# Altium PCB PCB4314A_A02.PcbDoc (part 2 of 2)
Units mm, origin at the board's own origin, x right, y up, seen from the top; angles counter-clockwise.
Board outline 35.56 x 55.88 mm, 2 copper layers (Top Layer, Bottom Layer), stack 1.57 mm thick; 98 components, 71 nets, 413 pads, 418 vias.
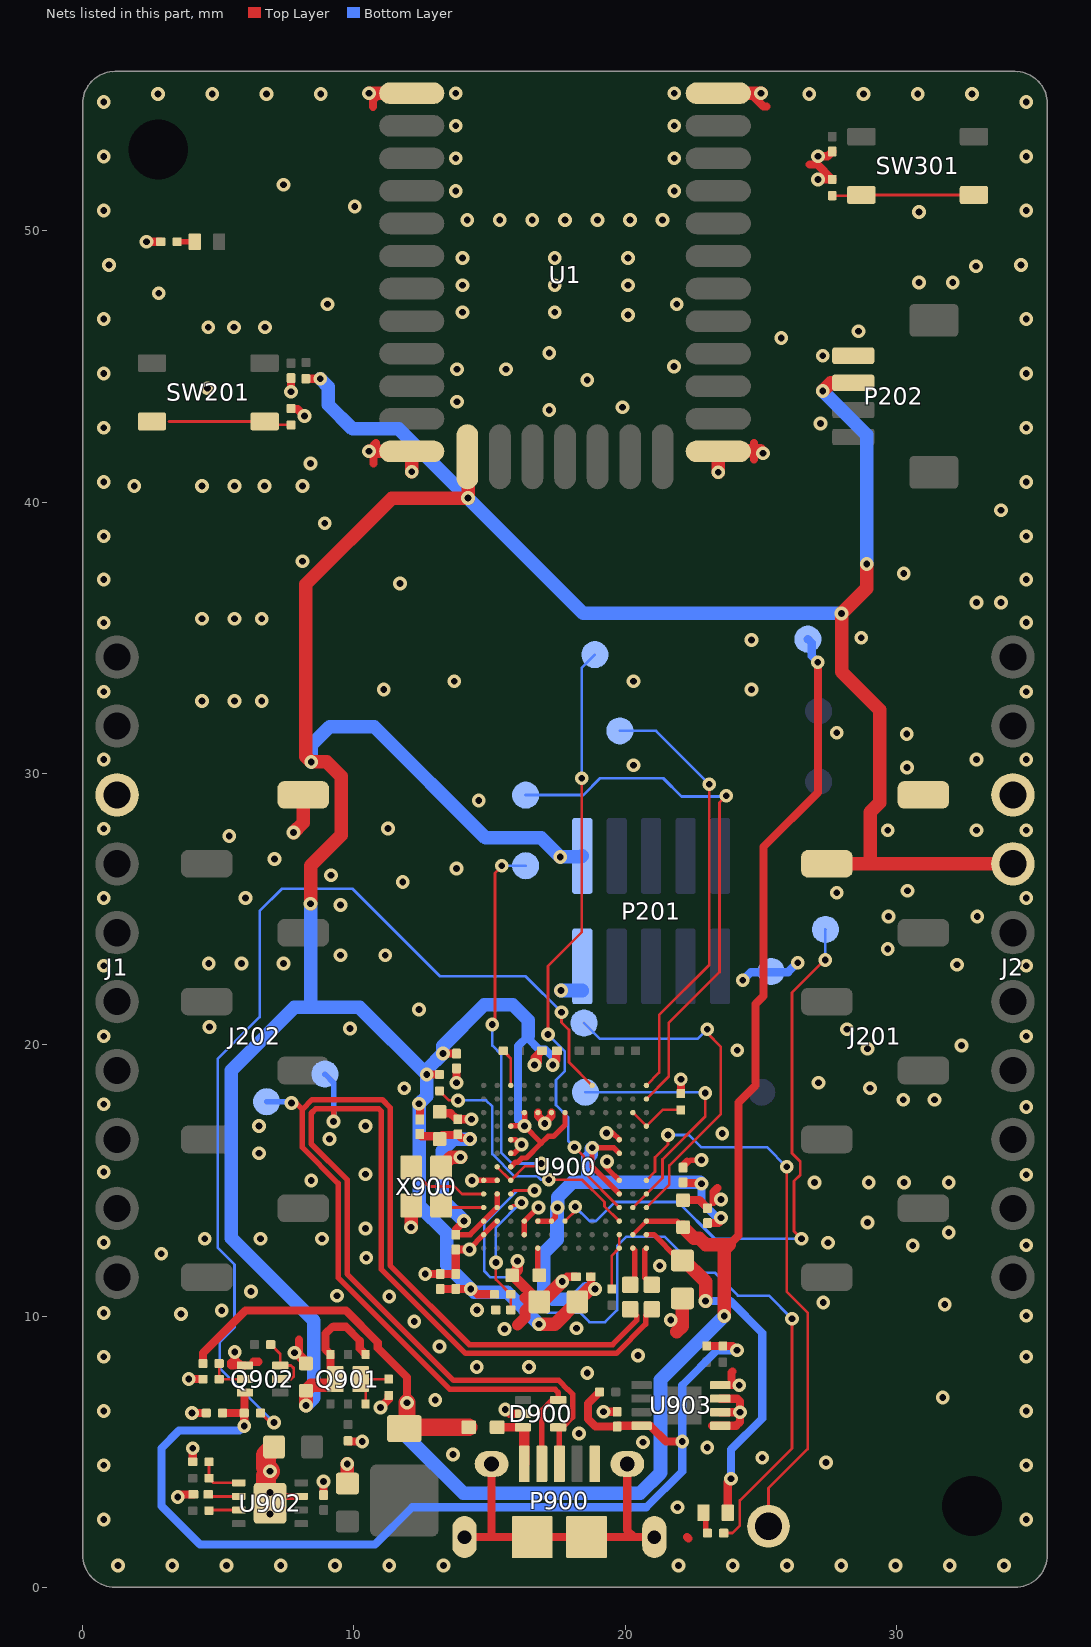
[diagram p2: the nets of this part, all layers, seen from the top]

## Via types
v1: diameter 0.508, hole 0.25, Top Layer to Bottom Layer, tented both sides, 418 vias

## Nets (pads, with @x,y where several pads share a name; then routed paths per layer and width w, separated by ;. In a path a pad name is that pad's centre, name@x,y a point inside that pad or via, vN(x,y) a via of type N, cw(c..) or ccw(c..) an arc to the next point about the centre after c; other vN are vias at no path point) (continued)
CTRL_MCU_PB10: R905.1 U900.L9 | length 30.2
  Top Layer w0.1: U900.L9@15.78,14.5 15.905,14.625 v1(16.655,14.625) ; R905.1@23.63,2 23.95,2 24.225,2.275 24.225,3.2 26.15,5.125 v1(26.15,9.9)
  Bottom Layer w0.1: v1(16.655,14.625) 16.023,14.625 14.802,13.404 14.802,11.654 15.031,11.425 15.85,11.425 17.15,10.125 18.325,10.125 18.675,9.775 19.25,9.775 19.7,10.225 19.7,12.575 20.05,12.925 21.45,12.925 22.775,11.6 23.3,11.6 24.15,10.75 25.3,10.75 v1(26.15,9.9)
CTRL_MCU_PB13: U900.N9 X900.3 | length 3.1
  Top Layer w0.1: X900.3@12.106,15.475 12.106,15.425 12.756,14.775 13.706,14.775 13.981,14.5 U900.N9@14.78,14.5
CTRL_MCU_PB14: U900.N10 X900.1 | length 1.7
  Top Layer w0.1: X900.1@13.231,14.04 13.201,14.07 X900.1@13.206,14.075 13.281,14 U900.N10@14.78,14
CTRL_MCU_PC2: R921.1 U900.L1 | length 1.4
  Top Layer w0.1: R921.1@15.505,19.775 15.515,19.775 15.612,19.678 15.612,19.668 15.78,19.5 U900.L1@15.78,18.5
CTRL_MCU_PC14: R922.1 U900.C12 U900.C13 | length 2.1
  Top Layer w0.1: R922.1@19.506,11 19.506,12.226 U900.C13@19.78,12.5 U900.C12@19.78,13
CTRL_MCU_PD0: C923.1 R901.1 U900.L10 | length 5.4
  Top Layer w0.1: v1(15.231,11.975) 15.231,11.349 R901.1@15.78,10.8 C923.1@15.78,10.225 ; U900.L10@15.78,14 15.855,14.075 16.055,14.075 v1@16.288,14.308
  Bottom Layer w0.1: v1(15.231,11.975) 15.231,13.26 v1@16.204,14.233 ; v1@16.204,14.201 v1@16.204,14.233 ; v1@16.205,14.268 16.223,14.251 v1@16.204,14.233 ; v1@16.281,14.326 v1@16.288,14.326
  other v1: 16.18,14.175
CTRL_MCU_PE4: R931.1 U900.C11 | length 9.7
  Top Layer w0.1: R931.1@13.155,18.3 13.505,17.95 v1(13.831,17.95) ; v1(17.181,15.025) 18.408,15.025 19.237,14.196 19.237,14.043 U900.C11@19.78,13.5
  Bottom Layer w0.1: v1(13.831,17.95) 14.875,17.95 15.1,17.725 15.1,15.975 15.925,15.15 16.775,15.15 16.9,15.025 v1(17.181,15.025)
CTRL_MCU_PE11: R935.1 U900.A4 U900.B3 | length 2.2
  Top Layer w0.1: U900.B3@20.28,17.5 U900.A4@20.78,17 21.38,17.6 R935.1@22.05,17.6
CTRL_MCU_PF5: TP999.1 U900.A8 | length 21
  Top Layer w0.1: U900.A8@20.78,15 21.1,15.32 21.1,15.85 21.575,16.325 v1(21.575,16.675) ; TP999.1@25.28,2.25 25.28,3.655 26.725,5.1 26.725,10.125 25.95,10.9 v1(25.95,15.5)
  Bottom Layer w0.1: v1(21.575,16.675) 22.35,16.675 22.8,16.225 25.225,16.225 v1(25.95,15.5)
CTRL_MCU_PF10: R903.2 U900.B13 | length 1.5
  Top Layer w0.2: R903.2@20.18,11.15 20.357,11.327 20.357,12.423 U900.B13@20.28,12.5
CTRL_MCU_PF11: R904.2 U900.A13 | length 1.5
  Top Layer w0.2: U900.A13@20.78,12.5 20.719,12.44 20.719,11.411 R904.2@20.98,11.15
CTRL_MCU_RESET: TPJ17.1 U900.L8 U900.M7 | length 15.5
  Top Layer w0.1: v1(15.1,20.75) 15.2,20.85 15.2,26.325 v1@15.475,26.6 ; U900.M7@15.28,15.5 U900.L8@15.78,15 16.305,15.525 16.8,15.525 v1(16.9,15.625)
  Bottom Layer w0.1: v1(15.1,20.75) 15.1,19.975 15.425,19.65 15.425,16.025 15.825,15.625 v1(16.9,15.625) ; v1(15.45,26.6) TPJ17.1@16.33,26.6
CTRL_MCU_RXD: TPJ6.1 U900.A1 | length 16.2
  Top Layer w0.1: U900.A1@20.78,18.5 21.25,18.97 21.25,21.1 23.1,22.95 v1(23.1,29.6)
  Bottom Layer w0.1: TPJ6.1@19.8,31.57 21.13,31.57 v1(23.1,29.6)
CTRL_MCU_SWCLK: TPJ2.1 U900.C10 | length 22.4
  Top Layer w0.1: v1(17.15,20.375) 17.15,22.9 18.4,24.15 v1@18.4,29.775 ; v1(18.125,16.225) 18.475,15.875 18.475,15.305 U900.C10@19.78,14
  Bottom Layer w0.1: v1(17.15,20.375) 17.775,19.75 17.775,19.025 17.45,18.7 17.45,17.775 17.9,17.325 17.9,16.45 v1(18.125,16.225) ; v1(18.4,29.825) 18.4,33.9 TPJ2.1@18.88,34.38
CTRL_MCU_SWDIO: TPJ1.1 U900.A9 U900.B10 | length 9.8
  Top Layer w0.1: U900.B10@20.28,14 U900.A9@20.78,14.5 21.375,15.095 21.375,15.775 22.95,17.35 v1(22.95,18.225)
  Bottom Layer w0.1: TPJ1.1@18.53,18.25 22.925,18.25 v1(22.95,18.225)
CTRL_MCU_SWO: TPJ3.1 U900.A10 | length 12.8
  Top Layer w0.1: U900.A10@20.78,14 21.625,14.845 21.625,15.55 23.525,17.45 23.525,19.925 23.025,20.425 v1(23.025,20.575)
  Bottom Layer w0.1: TPJ3.1@18.48,20.8 19.055,20.225 22.675,20.225 v1(23.025,20.575)
CTRL_MCU_TEST_MODE: TPJ11.1 U900.G11 | length 22.5
  Top Layer w0.1: U900.G11@17.78,13.5 18.23,13.95 v1@18.23,14.175
  Top Layer w0.102: v1(26.5,12.85) 26.225,13.125 26.225,14.975 26.45,15.2 26.45,15.7 26.15,16 26.15,21.925 27.35,23.125 v1(27.375,23.125)
  Bottom Layer w0.102: v1(18.156,14.025) 18.681,13.5 18.925,13.5 19.625,14.2 21.95,14.2 23.3,12.85 v1(26.5,12.85) ; v1(27.375,23.125) 27.375,24.245 TPJ11.1@27.38,24.25
CTRL_MCU_TXD: TPJ5.1 U900.A2 | length 20.3
  Top Layer w0.1: U900.A2@20.78,18 21.6,18.82 21.6,20.8 23.475,22.675 23.475,28.925 v1(23.725,29.175)
  Bottom Layer w0.1: TPJ5.1@16.33,29.2 16.325,29.205 18.455,29.205 19.075,29.825 21.4,29.825 22.075,29.15 23.7,29.15 v1(23.725,29.175)
CTRL_MCU_USB_DM: D900.5 P900.2 R903.1 TPJ19.1 | length 41.4
  Top Layer w0.203: v1(7.7,17.85) 7.857,17.85 8.095,17.612 ; P900.2@16.925,4.55 16.925,6.52 17.305,6.9 D900.5@17.53,6.9 17.53,7.178 17.413,7.295 13.538,7.295 9.42,11.413 9.42,14.888 8.095,16.213 8.095,17.612 ; R903.1@20.18,10.25 20.42,10.01 20.42,9.837 19.533,8.95 14.25,8.95 11.33,11.87 11.33,17.687 11.042,17.975 8.458,17.975 8.095,17.612
  Bottom Layer w0.203: TPJ19.1@6.78,17.9 v1@7.6,17.9
CTRL_MCU_USB_DP: D900.4 P900.3 R904.1 TPJ18.1 | length 42.4
  Top Layer w0.203: v1(9.25,17.175) 9.25,17.645 ; P900.3@17.575,4.55 17.575,5.855 D900.4@17.53,5.9 17.68,5.9 18.057,6.277 18.057,6.675 18.059,6.677 18.059,7.116 18.059,7.123 17.903,7.279 17.896,7.279 17.55,7.625 13.675,7.625 9.75,11.55 9.75,15.025 8.425,16.35 8.425,17.475 8.595,17.645 9.25,17.645 ; R904.1@20.98,10.25 20.75,10.02 20.75,9.7 19.67,8.62 14.113,8.62 11,11.733 11,17.55 10.905,17.645 9.25,17.645
  Bottom Layer w0.203: TPJ18.1@8.93,18.92 9.25,18.6 v1@9.25,17.275
CTRL_MCU_WAKEUP: R929.1 U900.E1 | length 38
  Top Layer w0.1: R929.1@6.555,6.425 6.565,6.425 6.915,6.075 v1(7.056,6.075) ; v1(17.65,21.2) 17.65,20.825 17.925,20.55 17.925,19.355 U900.E1@18.78,18.5
  Bottom Layer w0.1: v1(7.056,6.075) 5.05,8.081 5.05,9.025 5.6,9.575 5.6,11.9 4.975,12.525 4.975,19.475 6.525,21.025 6.525,24.925 7.35,25.75 9.95,25.75 13.175,22.525 16.325,22.525 v1(17.65,21.2)
DBG_3V3: C919.1 Q902.3 R910.2 R911.2 R912.2 R929.2 R933.1 U903.8 | length 40.4
  Top Layer w0.3: R933.1@5.155,6.425 R929.2@5.955,6.425 5.957,6.425 5.967,6.435 5.967,7.175 Q902.3@5.98,7.175 ; v1@5.956,5.951 R929.2@5.955,6.425 ; R912.2@19.05,7.2 18.625,6.775 18.625,6.2 18.9,5.925 C919.1@19.7,5.925 19.73,5.955 U903.8@20.602,5.955 20.92,5.955 21.5,5.375 v1(22.1,5.375) ; R911.2@23,8.9 R910.2@23.6,8.9 23.96,8.9 v1(24.121,8.739)
  Bottom Layer w0.3: v1(5.956,5.95) 5.781,5.775 3.55,5.775 2.9,5.125 2.9,3 4.325,1.575 10.775,1.575 12.15,2.95 20.775,2.95 22.1,4.275 v1(22.1,5.375) 22.1,7.45 23.389,8.739 v1(24.121,8.739)
DBG_VBUS: C901.1 D901.2 L901.2 R917.2 TPJ12.1 U900.A11 U900.B12 | length 63.1
  Top Layer w0.152: U900.B12@20.28,13 U900.A11@20.78,13.5
  Top Layer w0.2: U900.A11@20.78,13.5 21.905,13.5 C901.1@22.13,13.275
  Top Layer w0.3: R917.2@4.431,8.25 4.431,8.631 6,10.2 9.705,10.2 10.875,9.03 10.875,8.825 11.956,7.744 v1(11.956,6.8) ; 23.825,12.625 24.175,12.975 24.175,17.875 24.8,18.5 24.8,21.5 25.1,21.8 25.1,27.3 27.1,29.3 27.1,30.475 v1(27.1,34.1)
  Top Layer w0.5: C901.1@22.13,13.275 22.535,12.87 22.73,12.87 22.975,12.625 23.825,12.625 23.65,12.45 v1(23.65,10)
  Top Layer w0.635: D901.2@11.855,5.85 D901.2@11.905,5.9 ; v1(11.956,6.8) 11.956,5.951 D901.2@11.905,5.9 ; L901.2@14.23,5.9 D901.2@11.905,5.9
  Bottom Layer w0.3: TPJ12.1@26.73,34.95 26.875,34.805 26.875,34.325 v1(27.1,34.1)
  Bottom Layer w0.5: v1(11.956,6.8) 11.956,5.544 14.025,3.475 20.558,3.475 21.3,4.217 21.3,7.65 v1(23.65,10)
DBG_VREGO: C902.1 LED900.1 U900.A12 | length 13.3
  Top Layer w0.2: U900.A12@20.78,13 21.055,13 C902.1@21.93,12.125
  Top Layer w0.3: LED900.1@23.78,2.75 23.78,3.88 v1(23.9,4)
  Top Layer w0.305: C902.1@21.93,12.125 C902.1@22.105,12.125
  Top Layer w0.5: C902.1@22.105,12.125 22.96,11.27 v1(22.96,10.55)
  Bottom Layer w0.3: v1(22.96,10.55) 23.875,10.55 25.05,9.375 25.05,6.225 23.9,5.075 v1(23.9,4)
GND: C201.2 C301.2 C900.2 C901.2 C902.2 C903.2 C904.2 C905.2 C907.2 C908.2 C909.2 C910.2 C911.2 C915.2 C916.2 C917.2 C918.2 C919.2 C920.2 C923.2 C924.2 C925.2 C926.2 D900.2 J1.3 J2.3 J201.8 J202.8 P201.2 P202.1 P900.5 P900.6 P900.7 P900.8 P900.9 P900.10 P900.11 Q902.1 R202.2 R203.1 R301.1 R909.1 R915.1 R916.1 R933.2 R934.1 R935.2 TPJ13.1 U1.1 U1.12 U1.20 U1.31 U900.C5 U900.C8 U900.H3 U900.J3 U900.K11 U900.K12 U900.L5 U900.L6 U900.M8 U900.M11 U900.N8 U900.N12 U902.3 U902.9 U903.1 U903.2 U903.3 U903.4 X900.2 X900.4 | length 73.9
  Top Layer w0.1: C903.2@13.155,17.525 C903.2@13.18,17.5
  Top Layer w0.2: v1@14.255,17.15 v1@14.381,17.15 ; v1(14.254,12.451) 14.256,12.476 U900.N12@14.78,13 U900.M11@15.28,13.5 ; v1(14.356,15) U900.N8@14.78,15 U900.M8@15.28,15 ; U900.L6@15.78,16 15.903,16 16.179,16.276 15.956,16.5 U900.L5@15.78,16.5 ; U900.K12@16.28,13 U900.K11@16.28,13.5 16.805,14.025 16.855,14.025 v1@16.88,14.05 ; v1@19.274,15.709 v1@19.317,15.709 ; v1(19.307,16.749) 19.531,16.749 U900.C5@19.78,16.5 ; v1@19.33,15.722 v1@19.317,15.709 ; U900.C8@19.78,15 19.374,15.406 ; C910.2@22.151,15.454 C910.2@22.13,15.475 C910.2@22.13,15.495 ; 22.275,15.75 22.13,15.605 C910.2@22.13,15.495 ; v1(22.806,15.75) 22.405,15.75 22.21,15.555 22.19,15.555 C910.2@22.13,15.495 ; v1@19.255,15.646 19.374,15.527 19.374,15.406 ; v1@19.255,15.646 19.255,15.525 19.374,15.406 ; v1@19.255,15.647 v1@19.317,15.709
  Top Layer w0.25: U902.9@7.155,3.35 U902.3@8.055,3.35
  Top Layer w0.3: v1(2.356,49.6) 2.86,49.6 2.87,49.61 R203.1@2.88,49.6 ; v1(3.506,3.325) 3.606,3.425 C918.2@4.081,3.425 ; v1(3.906,7.675) R916.1@4.431,7.675 ; v1(4.031,6.425) R933.2@4.555,6.425 ; R909.1@4.056,4.625 v1(4.056,5.125) ; 5.476,8.287 5.476,8.175 Q902.1@5.98,8.175 ; v1(5.606,8.675) 5.606,8.399 Q902.1@5.83,8.175 ; 6.3,8.325 6.312,8.313 6.48,8.313 ; v1(7.806,8.65) 7.931,8.65 v1@7.975,8.606 ; 7.975,9.125 v1@7.975,8.606 ; C920.2@8.231,8.25 7.975,8.506 v1@7.975,8.606 ; C920.2@8.331,8.25 v1@7.975,8.606 ; C916.2@8.88,3.4 C916.2@8.881,3.401 ; C916.2@8.881,3.402 v1@8.881,3.849 ; R915.1@9.781,5.4 9.781,5.39 9.791,5.38 10.301,5.38 v1(10.306,5.375) ; 10.7,54.575 10.7,54.825 U1.1@10.95,55.075 ; 10.725,41.425 10.725,41.875 10.725,42.093 10.812,42.18 ; v1(10.975,6.625) 11.28,6.93 R934.1@11.28,7.075 ; C925.2@13.78,19.125 C925.2@13.78,19.125 v1(13.781,18.6) ; P900.8@14.075,1.85 15.005,1.85 ; P900.6@15.075,4.55 15.075,1.92 15.005,1.85 ; 16.775,19.6 16.775,19.369 v1(16.656,19.25) 16.656,19.521 16.91,19.775 C908.2@16.93,19.775 ; v1(17.681,11.275) 17.856,11.45 C911.2@18.181,11.45 ; P900.7@20.075,4.55 20.075,2.105 20.33,1.85 ; P900.9@21.075,1.85 20.33,1.85 ; R935.2@22.05,18.2 v1(22.05,18.725) ; C901.2@22.13,14.275 22.73,14.275 C926.2@23.03,13.975 ; 22.275,1.85 22.325,1.8 ; 23.25,14.2 23.25,14.575 23.4,14.725 ; U903.4@23.502,7.455 24.195,7.455 v1(24.2,7.45) ; 23.916,7.682 23.916,7.916 23.95,7.95 ; U1.31@24.6,55.075 25.092,54.584 25.208,54.584 ; 24.748,41.57 24.748,41.9 24.748,42.18 ; 26.8,52.45 27.08,52.45 R301.1@27.63,51.9 ; v1(27.106,51.9) R301.1@27.63,51.9 ; v1(27.106,52.75) 27.455,52.75 27.6,52.895 27.62,52.895 27.63,52.905 C301.2@27.63,52.925 ; R301.1@27.62,51.92 27.63,51.91 R301.1@27.63,51.9 ; 15.005,1.85 P900.10@16.575,1.85 P900.11@18.575,1.85 20.33,1.85
  Top Layer w0.305: R202.2@7.68,43.45 7.68,43.44 7.687,43.432 7.924,43.432 v1(8.181,43.175) ; C201.2@7.68,44.575 7.681,44.574 v1(7.681,44.075) ; v1(12.63,11.55) C909.2@13.18,11.55 C924.2@13.755,11.55 C904.2@13.755,12.45 14.255,12.45 v1(14.254,12.451) ; C903.2@13.155,17.475 13.564,17.475 13.745,17.294 13.786,17.294 C905.2@13.83,17.25 14.228,17.25 v1@14.255,17.223 ; v1(14.254,12.451) v1(14.254,12.451) ; v1@14.28,12.475 v1(14.254,12.451) ; v1(15.58,6.55) 15.73,6.4 D900.2@16.23,6.4 ; U900.J3@16.78,17.5 16.78,17.374 17.031,17.123 17.28,17.371 U900.H3@17.28,17.5 ; v1(19.2,6.475) C919.2@19.7,6.475 ; U903.1@23.205,5.955 U903.1@23.502,5.955 23.505,5.958 24.089,5.958 24.226,6.095 v1@24.226,6.455 ; U903.3@23.502,6.955 23.505,6.953 24.128,6.953 24.226,6.855 v1@24.226,6.455 ; U903.2@23.505,6.458 U903.2@23.502,6.455 v1@24.226,6.455
  Top Layer w0.4: 16.025,9.675 16.3,9.95 16.3,10.2 C907.2@16.625,10.525 ; v1(16.03,12.032) 16.03,11.7 C900.2@15.83,11.5 15.856,11.5 C907.2@16.831,10.525 C907.2@16.625,10.525 ; 16.3,10.675 16.45,10.525 C907.2@16.625,10.525
  Top Layer w0.5: J1.3@1.246,29.21 J1.3@1.27,29.21 ; v1(7.775,27.825) 8.129,28.179 J202.8@8.129,29.21 ; C915.2@9.755,3.825 9.756,3.826 v1(9.756,4.55) ; v1(10.556,41.875) 10.725,41.875 U1.12@12.13,41.875 12.131,41.874 v1(12.131,41.125) ; v1(10.556,55.075) 10.95,55.075 U1.1@12.13,55.075 ; v1(12.106,13.275) X900.4@12.106,14.075 ; X900.2@13.206,15.475 13.581,15.85 v1(13.931,15.85) ; C907.2@16.831,10.525 16.931,10.525 v1(17.681,11.275) ; 21.9,9.425 22.106,9.631 C902.2@22.106,10.65 ; U1.31@23.43,55.075 24.6,55.075 v1(25.004,55.075) ; v1(23.431,41.1) 23.431,41.874 U1.20@23.43,41.875 23.455,41.9 24.748,41.9 v1@24.981,41.9 ; J201.8@30.381,29.21 J201.8@30.989,29.21
  Top Layer w0.75: U902.9@6.905,3.5 U902.9@6.905,3.1 6.755,3.25 6.755,4.124 v1(6.906,4.275) 6.755,4.426 6.755,4.875 C917.2@7.055,5.175
  Bottom Layer w0.305: v1@15.98,12.082 v1(16.03,12.032) ; v1(24.331,22.375) 24.631,22.675 26.006,22.675 v1(26.356,23.025)
  Bottom Layer w0.5: v1(17.631,22) 18.406,22 P201.2@18.416,21.99
  other v1: 1.3,0.8 3.3,0.8 5.3,0.8 7.3,0.8 9.3,0.8 11.3,0.8 13.3,0.8 21.96,0.8 23.96,0.8 25.96,0.8 27.96,0.8 29.96,0.8 31.96,0.8 33.96,0.8 0.775,2.5 34.785,2.5 6.906,2.7 21.925,2.95 6.906,3.5 8.881,3.9 0.775,4.5 34.785,4.5 27.4,4.6 25.05,4.775 13.65,4.9 23.025,5.15 20.65,5.35 18.3,5.675 24.231,6.45 0.775,6.5 34.785,6.5 13,6.9 31.7,7 18.6,7.9 14.525,8.125 16.45,8.125 0.775,8.5 34.785,8.5 20.475,8.55 13.15,8.875 15.55,9.525 18.2,9.55 12.225,9.8 21.675,9.85 34.785,10.01 3.625,10.075 0.775,10.11 5.125,10.2 14.531,10.225 31.775,10.425 27.3,10.5 11.3,10.725 9.375,10.75 6.2,10.9 21.275,11.85 10.45,12.15 2.9,12.3 30.6,12.6 34.785,12.61 27.475,12.7 0.775,12.71 4.5,12.85 6.55,12.85 8.825,12.85 31.925,13.075 10.425,13.225 28.925,13.45 16.806,14 23.531,14.3 26.975,14.925 28.975,14.925 30.275,14.925 31.925,14.925 8.425,15 34.785,15.21 10.425,15.225 0.775,15.31 19.33,15.7 6.5,16 16.18,16.325 9.1,16.525 23.576,16.732 6.5,17 10.425,17 17.031,17.1 14.331,17.25 34.785,17.71 0.775,17.81 30.25,17.975 31.4,17.975 11.85,18.4 29.025,18.4 27.125,18.6 24.125,19.8 28.925,19.85 32.4,19.975 0.775,20.31 34.785,20.31 28.175,20.575 9.85,20.6 4.675,20.65 12.4,21.3 0.775,22.91 34.785,22.91 32.225,22.95 4.65,23 5.85,23 7.4,23 9.5,23.3 11.15,23.3 29.675,23.525 29.7,24.725 32.975,24.725 9.5,25.15 0.775,25.41 6,25.41 34.785,25.41 27.8,25.6 30.4,25.675 11.8,26 9.15,26.25 13.775,26.5 7.075,26.85 5.4,27.7 29.675,27.91 32.95,27.91 34.785,27.91 0.775,27.96 11.25,27.975 14.6,29 30.381,30.225 20.3,30.3 0.775,30.51 32.95,30.51 34.785,30.51 30.375,31.45 27.8,31.5 4.4,32.675 5.6,32.675 6.6,32.675 0.775,33.01 34.785,33.01 11.1,33.1 24.65,33.1 13.7,33.4 20.3,33.4 24.65,34.925 28.7,35 0.775,35.56 34.785,35.562 4.4,35.7 5.6,35.7 6.6,35.7 32.95,36.3 33.85,36.3 11.7,37 0.775,37.148 34.785,37.148 30.266,37.376 8.1,37.825 0.775,38.748 34.785,38.748 8.925,39.225 33.85,39.7 1.9,40.6 4.4,40.6 5.6,40.6 6.7,40.6 8.1,40.6 0.775,40.748 34.785,40.748 8.4,41.425 25.076,41.802 0.775,42.748 34.785,42.748 27.2,42.9 17.2,43.4 19.9,43.5 13.8,43.7 4.6,44.2 18.6,44.5 0.775,44.748 34.785,44.748 13.8,44.9 15.6,44.9 21.8,45 27.281,45.4 17.2,45.5 25.75,46.05 28.6,46.3 4.625,46.45 5.575,46.45 6.725,46.45 0.775,46.748 34.785,46.748 20.1,46.9 14,47 17.4,47 9.025,47.3 21.9,47.3 2.8,47.7 14,48 17.4,48 20.1,48 30.825,48.1 32.075,48.1 32.925,48.7 0.975,48.748 34.585,48.748 14,49 17.4,49 20.1,49 14.175,50.4 15.375,50.4 16.575,50.4 17.775,50.4 18.975,50.4 20.175,50.4 21.375,50.4 30.825,50.7 0.775,50.748 34.785,50.748 10.025,50.9 13.75,51.475 21.81,51.475 7.4,51.7 13.75,52.675 21.81,52.675 0.775,52.748 34.785,52.748 13.75,53.875 21.81,53.875 0.775,54.748 34.785,54.748 2.775,55.048 4.775,55.048 6.775,55.048 8.775,55.048 26.785,55.048 28.785,55.048 30.785,55.048 32.785,55.048 13.75,55.075 21.81,55.075
N16782098: LED201.2 R203.2 | length 0.7
  Top Layer w0.2: R203.2@3.48,49.6 LED201.2@4.13,49.6
N16786878: R202.1 SW201.3 SW201.4 | length 4.6
  Top Layer w0.1: 3.181,42.975 SW201.4@6.705,42.975 6.83,42.85 R202.1@7.68,42.85
N16788367: D900.3 L901.1 P900.1 | length 2.2
  Top Layer w0.3: L901.1@15.28,5.9 D900.3@16.155,5.9 ; D900.3@16.23,5.9 16.23,5.825 D900.3@16.275,5.78
  Top Layer w0.4: P900.1@16.275,4.55 D900.3@16.275,5.78
N16788394: R908.1 R909.2 U902.5 | length 1.8
  Top Layer w0.1: R909.2@4.656,4.625 R908.1@4.656,4.025 4.831,3.85 U902.5@5.755,3.85
N16788408: R907.1 U902.7 | length 1.1
  Top Layer w0.1: R907.1@4.656,2.825 4.681,2.85 U902.7@5.755,2.85
N16788424: C918.1 U902.6 | length 1.2
  Top Layer w0.1: C918.1@4.631,3.425 4.706,3.35 U902.6@5.755,3.35
N16791923: LED900.2 R905.2 | length 0.9
  Top Layer w0.2: LED900.2@22.88,2.675 LED900.2@22.88,2.75 22.96,2.67 22.96,2.06 23.02,2 R905.2@23.03,2
N16793325: C900.1 U900.J13 | length 1
  Top Layer w0.2: C900.1@16.78,11.5 U900.J13@16.78,12.5
N16793347: C903.1 C904.1 C905.1 L900.2 U900.M9 U900.M10 U900.N11 | length 9.4
  Top Layer w0.2: C904.1@13.755,13 14.28,13 U900.N11@14.78,13.5 U900.M10@15.28,14 U900.M9@15.28,14.5
  Top Layer w0.3: C904.1@13.755,13 13.755,13.199 v1(14.056,13.5)
  Top Layer w0.305: L900.2@12.43,16.705 12.43,16.68 12.487,16.623 13.057,16.623 C903.1@13.105,16.575 ; C903.1@13.155,16.525 C903.1@13.105,16.575 ; C905.1@13.83,16.7 13.83,16.68 13.822,16.672 13.252,16.672 13.155,16.575 C903.1@13.105,16.575 ; C905.1@13.83,16.7 13.831,16.679 13.838,16.672 13.858,16.672 13.966,16.564 14.292,16.564 v1@14.331,16.525
  Bottom Layer w0.5: v1(14.056,13.5) 13.256,14.3 13.256,16.1 13.68,16.523 14.28,16.523 v1(14.281,16.525)
N16822845: R301.2 SW301.3 SW301.4 | length 5.2
  Top Layer w0.1: R301.2@27.63,51.3 28.68,51.3 SW301.3@28.705,51.325 SW301.4@32.855,51.325
N16862939: Q901.3 Q901.8 R934.2 | length 2
  Top Layer w0.1: Q901.3@10.43,6.763 10.43,7.491 Q901.8@10.246,7.675 R934.2@11.28,7.675
N16974649: Q902.2 R916.2 R917.1 | length 1.5
  Top Layer w0.1: R917.1@5.031,8.25 R916.2@5.031,7.675 Q902.2@5.98,7.675
N16974657: Q902.5 Q902.6 R918.1 | length 2.3
  Top Layer w0.1: R918.1@6.93,8.95 6.94,8.95 7.28,8.61 Q902.6@7.28,8.175 7.681,8.175 7.781,8.075 7.781,7.775 7.681,7.675 Q902.5@7.28,7.675
VMCU: C907.1 C908.1 C909.1 C910.1 C911.1 C920.1 C924.1 C925.1 C926.1 J2.4 J201.7 L900.1 P201.1 P202.2 Q901.4 Q901.6 Q901.7 R201.1 R901.2 R931.2 U1.13 U900.C6 U900.C9 U900.G3 U900.H11 U900.J11 U900.K3 U900.L4 U900.L7 | length 172.8
  Top Layer w0.2: U900.L7@15.78,15.5 15.955,15.675 16.038,15.675 16.188,15.825 16.357,15.825 16.904,16.371 ; U900.L4@15.78,17 15.8,17.02 v1@16.23,17.02 ; v1@16.23,17 16.288,17.058 16.288,17.492 U900.K3@16.28,17.5 ; v1(16.281,17) 16.904,16.378 16.904,16.371 ; U900.J11@16.78,13.5 U900.H11@17.28,13.5 17.426,13.646 v1@17.426,13.796 ; U900.G3@17.78,17.5 17.78,17.049 17.352,16.621 17.153,16.621 16.904,16.371 ; v1@18.776,15.979 18.776,15.504 U900.C9@19.78,14.5 ; v1(18.781,16.2) 19.58,16.2 U900.C6@19.78,16
  Top Layer w0.25: v1@18.907,11.049 v1@18.956,11
  Top Layer w0.3: R201.1@8.23,44.55 v1(8.756,44.55) ; Q901.7@9.313,7.675 9.313,7.843 9.13,8.027 Q901.6@9.13,8.588 8.95,8.767 8.95,9.35 9.2,9.6 9.258,9.6 9.262,9.604 9.7,9.604 10.215,9.09 10.215,8.803 Q901.4@10.43,8.588 ; v1(12.4,17.825) 12.43,17.795 L900.1@12.43,17.245 ; v1(12.681,18.9) R931.2@13.155,18.9 ; C909.1@13.18,11 C924.1@13.755,11 v1(14.306,11) 14.362,11 14.56,10.803 15.177,10.803 R901.2@15.18,10.8 ; v1(13.281,19.675) C925.1@13.78,19.675 ; v1@17.456,19.431 17.456,19.765 17.466,19.775 C908.1@17.48,19.775 ; v1@18.681,11 18.731,11.05 C911.1@18.731,11.45 ; C910.1@22.13,14.925 22.13,14.91 22.14,14.9 22.781,14.9 v1(22.806,14.875) ; C926.1@23.03,13.425 23.431,13.425 v1@23.506,13.5
  Top Layer w0.5: v1(8.231,6.7) C920.1@8.231,7.25 C920.1@8.431,7.45 ; v1(8.4,25.2) 8.4,26.6 9.525,27.725 9.525,29.9 9,30.425 v1(8.425,30.425) 8.225,30.625 8.225,36.975 11.4,40.15 v1(14.206,40.15) 14.206,41.649 U1.13@14.18,41.675 ; 8.531,7.45 9.257,7.45 9.313,7.506 Q901.7@9.313,7.675 ; v1(16.825,9.7) 17.406,9.7 C907.1@18.231,10.525 18.231,10.55 18.681,11 v1@18.832,11 ; v1(27.281,44.1) 27.581,44.4 P202.2@28.405,44.4 ; J201.7@27.433,26.67 29,26.67 ; v1@28.895,37.7 28.895,36.82 v1(27.975,35.9) 27.975,33.75 29.375,32.35 29.375,28.925 29.025,28.575 29.025,26.695 29,26.67 ; 31.55,26.675 31.545,26.67 ; J2.4@34.29,26.67 31.545,26.67 ; 29,26.67 31.545,26.67
  Bottom Layer w0.3: v1(16.281,17) 16.05,17.231 16.05,19.95 16.425,20.325 16.425,20.225 16.825,19.825 17.05,19.825 17.331,19.544 v1(17.331,19.25) ; v1(22.806,14.875) 22.806,14.194 23.375,13.625 v1(23.531,13.625)
  Bottom Layer w0.5: v1(8.231,6.7) 8.525,6.994 8.525,9.825 5.475,12.875 5.475,19.05 7.8,21.375 8.4,21.375 ; v1(8.4,25.2) 8.4,21.375 ; v1(8.425,30.425) 8.425,31.05 9.1,31.725 10.75,31.725 14.85,27.625 16.906,27.625 v1(17.606,26.925) 18.381,26.925 P201.1@18.416,26.96 ; v1(8.756,44.55) 8.756,44.548 9.056,44.248 9.056,43.594 9.95,42.7 11.65,42.7 14.2,40.15 v1(14.206,40.15) 18.456,35.9 v1(27.975,35.9) ; 16.425,20.325 16.425,20.9 15.85,21.475 14.8,21.475 13.281,19.956 v1(13.281,19.675) 12.681,19.075 v1(12.681,18.9) ; v1(16.825,9.7) 15.65,10.875 14.431,10.875 v1(14.306,11) 13.425,11.881 13.425,13.05 12.4,14.075 v1(12.4,17.825) 12.681,18.106 v1(12.681,18.9) ; v1(18.781,16.2) 18.754,16.173 18.754,15.964 18.625,15.835 18.625,14.925 ; v1(18.882,11) 18.55,11 18.175,10.625 17.325,10.625 17,10.95 17,12.325 17.485,12.81 17.485,13.979 v1(17.506,14) 17.506,14.381 18.05,14.925 18.625,14.925 ; v1(22.806,14.875) 22.756,14.925 18.625,14.925 ; v1(27.281,44.1) 28.895,42.487 v1@28.895,37.75 ; 8.4,21.375 10.206,21.375 v1(12.681,18.9)
  other v1: 28.9,37.725
pads on no net: D900.1 M900.7 M900.9 M901.1 M902.1 P202.5 P202.6 P900.4 U1.21 U900.A3 U900.A5 U900.A7 U900.B1 U900.B2 U900.B4 U900.B5 U900.B6 U900.B7 U900.B8 U900.B9 U900.B11 U900.C3 U900.C4 U900.C7 U900.D2 U900.D13 U900.E2 U900.E11 U900.E12 U900.E13 U900.F1 U900.F2 U900.F3 U900.F11 U900.F12 U900.G1 U900.G2 U900.G12 U900.H1 U900.H2 U900.J1 U900.J2 U900.K1 U900.K2 U900.K13 U900.L3 U900.L11 U900.L12 U900.L13 U900.M2 U900.M3 U900.M4 U900.M5 U900.M6 U900.M12 U900.M13 U900.N3 U900.N4 U900.N5 U900.N6 U900.N7 U900.N13 U902.8 U903.9

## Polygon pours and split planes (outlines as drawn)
GND on Top Layer "GND_L1" (solid, remove dead copper, pour order 52): 0,0 0,55.88 35.56,55.88 35.56,0
GND on Bottom Layer "GND_L4" (solid, remove dead copper, pour order 46): 0,0 0,55.88 35.56,55.88 35.56,0

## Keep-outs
Bottom Layer:
  circle w0.1: c28.63,22 r0.5
  circle w0.1: c26.23,26.75 r0.5
  circle w0.1: c19.8,29.05 r0.5
  circle w0.1: c17.27,31.53 r0.5
  circle w0.1: c16.38,33.9 r0.5
  circle w0.1: c24.625,42.635 r0.3

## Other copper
Top Layer:
  pour cut-out: 22.35,10.525 22.35,9.475 23.475,9.475 23.475,10.525
  pour cut-out: 24.225,48.2 24.1,48.2 24.1,48.775 24.225,48.775
  pour cut-out: 22.6,47.675 22.6,44.4 23.1,44.4 23.1,47.675
  pour cut-out: 12.95,43.275 12.95,44.1 12.65,44.1 12.65,43.275
  pour cut-out: 14.5,42.225 14.5,42.475 21.175,42.475 21.175,42.225
  pour cut-out: 14.1,24.1 17.2,24.1 17.2,24 16.2,23 14.1,23
  pour cut-out: 13.9,18.9 21.2,18.9 21.2,12.1 13.9,12.1
  region: 34.13,47.7 34.13,44.05 29.63,44.05 29.63,47.7
  region: 29.63,40.1 29.63,43.75 34.13,43.75 34.13,40.1
  region net BGM220P_RESETN: 33.53,54.15 33.53,52.75 31.43,52.75 31.43,54.15
  region net N16822845: 33.53,52 33.53,50.6 31.43,50.6 31.43,52
  region net N16822845: 28.03,50.65 28.03,52.05 30.13,52.05 30.13,50.65
  region net BGM220P_RESETN: 28.03,52.8 28.03,54.2 30.13,54.2 30.13,52.8
  region net N16786878: 5.28,42.3 5.28,43.7 7.38,43.7 7.38,42.3
  region net N16786878: 1.88,42.3 1.88,43.7 3.98,43.7 3.98,42.3
  pour cut-out: 14.266,13.425 14.256,13.435 14.256,16.115 11.531,16.115 11.531,13.425
  region net BGM220P_BUTTON0: 5.28,44.4 5.28,45.8 7.38,45.8 7.38,44.4
  region net BGM220P_BUTTON0: 1.88,44.4 1.88,45.8 3.98,45.8 3.98,44.4
Bottom Layer:
  pour cut-out: 20.487,1.563 20.487,2.148 cw(c21.069,2.148) 21.069,2.731 cw(c21.069,2.15) 21.65,2.15 21.65,1.5 cw(c21.1,1.5) 21.1,0.95 cw(c21.1,1.563)
  pour cut-out: 13.487,1.563 13.487,2.148 cw(c14.069,2.148) 14.069,2.731 cw(c14.069,2.15) 14.65,2.15 14.65,1.5 cw(c14.1,1.5) 14.1,0.95 cw(c14.1,1.563)
  pour cut-out: 19.325,4.55 cw(c19.925,4.55) 19.925,5.15 20.225,5.15 cw(c20.225,4.55) 20.825,4.55 cw(c20.225,4.55) 20.225,3.95 19.925,3.95 cw(c19.925,4.55)
  pour cut-out: 14.325,4.55 cw(c14.925,4.55) 14.925,5.15 15.225,5.15 cw(c15.225,4.55) 15.825,4.55 cw(c15.225,4.55) 15.225,3.95 14.925,3.95 cw(c14.925,4.55)

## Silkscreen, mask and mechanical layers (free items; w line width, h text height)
Top Overlay:
  lines w0.3: 5.08,30.48 7.62,33.02
  text "RST" at 29.447,49.3 h1
  text "LED0" at 2.747,48 h1
  text "BTN0" at 2.797,41 h1
  text "BGM220P" at 12.947,38.65 h1.8
  text "C7" at 2.262,33.94 h0.7
  text "RST" at 31.531,33.94 h0.7
  text "A4" at 2.262,31.4 h0.7
  text "A0" at 32.168,31.4 h0.7
  text "GND" at 11.198,29.56 h0.7 r180
  text "GND" at 26.004,29.56 h0.7 r180
  text "5V" at 11.288,27.02 h0.7 r180
  text "3V3" at 26.009,27.02 h0.7 r180
  text "SDA" at 11.198,24.48 h0.7 r180
  text "MOSI" at 25.96,24.48 h0.7 r180
  text "D3" at 2.262,23.78 h0.7
  text "C0" at 32.168,23.78 h0.7
  text "SCL" at 11.202,21.94 h0.7 r180
  text "MISO" at 25.986,21.94 h0.7 r180
  text "D2" at 2.262,21.24 h0.7
  text "C1" at 32.168,21.24 h0.7
  text "TX" at 11.253,19.4 h0.7 r180
  text "SCK" at 26.004,19.4 h0.7 r180
  text "B1" at 2.262,18.7 h0.7
  text "C2" at 32.168,18.7 h0.7
  text "RX" at 11.247,16.86 h0.7 r180
  text "CS" at 26.048,16.86 h0.7 r180
  text "B2" at 2.262,16.16 h0.7
  text "C3" at 32.168,16.16 h0.7
  text "INT" at 11.234,14.32 h0.7 r180
  text "RST" at 26.009,14.32 h0.7 r180
  text "B3" at 2.262,13.62 h0.7
  text "C6" at 32.168,13.62 h0.7
  text "PWM" at 11.585,11.78 h0.7 r180
  text "AN" at 26.048,11.78 h0.7 r180
  text "B4" at 2.262,11.08 h0.7
  text "B0" at 32.168,11.08 h0.7
  text "J-Link" at 21.605,3.45 h1
Bottom Overlay:
  circle w0.152: c25.28,2.25 r0.966
  lines w0.152: 10.88,50.616 10.88,49.616 11.88,49.616 ; 10.88,52.666 10.88,53.666 11.88,53.666 ; 23.38,49.616 24.38,49.616 24.38,50.616 ; 23.38,53.666 24.38,53.666 24.38,52.666
  text "BOARD INFO" at 24.38,54.181 h1.52
  text "PCB4314A Rev A02" at 33.63,39.55 h1.5 r270
  text "Mini Simplicity" at 24.281,29.8 h1.25
  text "1" at 17.581,26.6 h1.25
  text "2" at 17.581,22.4 h1.25
Top Solder:
  lines w0.8: -2.398,4.25 -2.398,1.189 ccw(c1.191,1.189) 1.191,-2.4 34.371,-2.4 ccw(c34.371,1.189) 37.96,1.189 37.96,4.25 ; -2.398,51.63 -2.398,54.795 cw(c1.139,54.743) 1.191,58.28 34.474,58.28 ; -2.397,4.25 -2.398,12.25 ; -2.398,16.75 -2.398,47.13 ; 0,54.808 0,1.19 ccw(c1.19,1.191) 1.191,0.001 ; 0,54.81 cw(c1.072,54.808) 1.074,55.88 ; 1.072,55.88 34.47,55.88 ; 1.191,0 34.369,0 ; 34.371,0 ccw(c34.371,1.189) 35.56,1.19 35.56,54.79 ; 34.374,58.262 cw(c34.474,54.778) 37.957,54.878 ; 34.468,55.88 cw(c34.47,54.79) 35.56,54.792 ; 37.959,54.778 37.959,51.63 37.96,51.63 ; 37.96,12.25 37.961,4.25 ; 37.96,16.75 37.96,47.13
Bottom Solder:
  lines w0.8: -2.398,1.189 ccw(c1.191,1.189) 1.191,-2.4 ; -2.398,16.75 -2.398,47.13 ; -2.398,51.63 -2.397,51.63 -2.397,54.709 ; -2.398,54.795 cw(c1.139,54.743) 1.191,58.28 ; -2.398,1.189 -2.398,4.25 -2.398,12.25 ; 0,44.4 0,1.189 ccw(c1.19,1.19) 1.191,0 ; 0.001,54.807 0.001,1.19 ccw(c1.191,1.191) 1.192,0.001 ; 0.001,54.808 cw(c1.074,54.807) 1.076,55.88 ; 1.074,55.88 34.469,55.88 ; 1.192,-2.4 34.372,-2.4 ; 1.192,0 34.37,0 ; 1.192,58.28 34.371,58.28 cw(c34.471,54.791) 37.96,54.891 ; 34.371,-2.4 ccw(c34.371,1.189) 37.96,1.189 ; 34.371,0 ccw(c34.371,1.189) 35.56,1.189 35.56,44.4 ; 34.372,0 ccw(c34.372,1.189) 35.561,1.19 35.561,54.788 ; 34.467,55.88 cw(c34.469,54.788) 35.561,54.79 ; 37.96,12.25 37.961,4.25 37.961,1.189 ; 37.96,16.75 37.96,47.13 ; 37.96,51.63 37.96,54.984
BOARD OUTLINE 1:
  drawing of 281 lines, arcs and shapes, not listed
  text "Milling (4 pcs)" at 12.405,2.95 h0.76
Mechanical 2:
  lines w0.1: -0.475,0 0.5,0 ; 0,-0.4 0,0.4 ; 17.306,0 18.281,0 ; 17.781,-0.4 17.781,0.4
Mechanical 12:
  lines w0.076: 1.191,0 34.369,0 ; 1.191,0.001 cw(c1.19,1.191) 0,1.19 0,54.693 cw(c1.189,54.691) 1.191,55.88 34.369,55.88 ; 34.369,55.88 cw(c34.371,54.691) 35.56,54.693 35.56,1.19 cw(c34.371,1.189) 34.371,0
Top Top assy 19/Bottom assy 20:
  lines w0.1: 1.191,0 34.369,0 ; 1.191,0.001 cw(c1.19,1.191) 0,1.19 0,54.693 cw(c1.189,54.691) 1.191,55.88 34.369,55.88 ; 34.369,55.88 cw(c34.371,54.691) 35.56,54.693 35.56,1.19 cw(c34.371,1.189) 34.371,0
  text "BGM220P" at 12.947,38.65 h1.8
Bottom Top assy 19/Bottom assy 20:
  lines w0.076: 1.191,0 34.369,0 ; 1.191,0.001 cw(c1.19,1.191) 0,1.19 0,54.693 cw(c1.189,54.691) 1.191,55.88 34.369,55.88 ; 34.369,55.88 cw(c34.371,54.691) 35.56,54.693 35.56,1.19 cw(c34.371,1.189) 34.371,0
  lines w0.1: 1.192,0 34.37,0 ; 1.192,0.001 cw(c1.191,1.191) 0.001,1.19 0.001,54.693 cw(c1.191,54.691) 1.192,55.88 34.37,55.88 cw(c34.372,54.691) 35.561,54.693 35.561,1.19 cw(c34.372,1.189) 34.372,0
Mechanical 26:
  lines w0.2: -117.029,-49.807 -112.029,-49.807 ; -117.029,-2.807 -112.029,-2.807 ; -117.017,44.193 -112.029,44.193 ; -45.821,-96.838 -45.821,-91.838 ; -45.821,88.162 -45.821,93.162 ; 25.479,-96.838 25.479,-91.838 ; 25.479,88.162 25.479,93.162 ; 96.679,-96.838 96.679,-91.838 ; 96.679,88.162 96.679,93.162 ; 162.971,-49.807 167.971,-49.807 ; 162.971,-2.807 167.971,-2.807 ; 162.971,44.193 167.959,44.193 ; -117.017,-96.838 -117.017,93.154 167.971,93.154 167.971,-96.838 -117.017,-96.838 ; -112.029,-91.838 -112.029,88.162 162.971,88.162 162.971,-91.838 -112.029,-91.838
  text "1" at -84.129,89.733 h1.52
  text "2" at -11.821,89.733 h1.52
  text "3" at 60.779,89.733 h1.52
  text "4" at 131.579,89.733 h1.52
  text "D" at 164.969,70.593 h1.52
  text "D" at -115.142,69.388 h1.52
  text "C" at -115.142,21.893 h1.52
  text "C" at 164.842,21.893 h1.52
  text "B" at -115.142,-25.707 h1.52
  text "B" at 164.842,-25.707 h1.52
  text "A" at -115.142,-73.207 h1.52
  text "A" at 164.842,-73.207 h1.52
  text "1" at -82.909,-95.28 h1.52
  text "2" at -11.821,-95.28 h1.52
  text "3" at 60.479,-95.28 h1.52
  text "4" at 131.179,-95.28 h1.52
Mechanical 27:
  circle w0.152: c78.907,-70.307 r0.762
  circle w0.152: c78.907,-70.307 r1.778
  circle w0.254: c46.923,-84.764 r2.962
  lines w0.152: 67.909,-70.307 75.275,-70.307 ; 76.621,-70.307 81.193,-70.307 ; 68.671,-71.069 74.488,-72.085 74.513,-68.529 68.671,-69.545 68.671,-71.069
  lines w0.2: 42.874,-91.698 42.874,-64.838 82.888,-64.838 ; 42.874,-77.474 162.839,-77.474 ; 42.888,-73.838 82.888,-73.838 ; 63.169,-91.647 63.169,-77.55 ; 63.169,-73.791 63.169,-64.875 ; 142.888,-77.448 142.888,-73.838 ; 152.888,-73.838 152.888,-64.838 ; 162.888,-73.838 82.888,-73.838 ; 162.888,-64.838 82.888,-64.838 ; 82.888,-73.838 82.888,-64.838
  text "SIZE" at 44.888,-66.838 h1.52
  text "DOC NO" at 84.888,-66.838 h1.52
  text "REV" at 154.888,-66.838 h1.52
  text "PROJECTION" at 64.185,-67.187 h1.52
  text "A" at 154.609,-71.759 h2.54
  text "BRD4314A (PCB4314 Rev A02)" at 85.21,-72.2 h2.54
  text "A4" at 47.538,-72.212 h2.54
  text "REF" at 44.888,-75.838 h1.52
  text "SHEET" at 143.888,-75.838 h1.52
  text "1 of 2" at 153.73,-76.875 h1.52
  text "This drawing is confidential and is supplied on the express" at 63.652,-80.446 h1.52
  text "condition that it shall not be loaned, copied or disclosed to any" at 63.652,-82.986 h1.52
  text "other person or used for any purpose without the written consent of" at 63.652,-85.526 h1.52
  text "C" at 46.329,-85.78 h2.03
  text "2020" at 51.409,-85.932 h2.54
  text "SILICON LABS" at 64.083,-89.818 h2.54
Mechanical 28:
  lines w0.2: -117.029,-49.807 -112.029,-49.807 ; -117.029,-2.807 -112.029,-2.807 ; -117.017,44.193 -112.029,44.193 ; 162.971,-49.807 167.971,-49.807 ; 162.971,-2.807 167.971,-2.807 ; 162.971,44.193 167.971,44.193
  lines w0.203: -112.054,-91.838 -112.054,88.162 ; -112.029,-91.838 162.971,-91.838 162.971,88.162 -112.029,88.162 ; -45.821,-96.838 -45.821,-91.838 ; -45.821,88.162 -45.821,93.162 ; 25.479,-96.838 25.479,-91.838 ; 25.479,88.162 25.479,93.162 ; 96.679,-96.838 96.679,-91.838 ; 96.679,88.162 96.679,93.162 ; -117.017,-96.838 167.971,-96.838 167.971,93.154 -117.017,93.154 -117.017,-96.838
  text "4" at -83.113,89.733 h1.52
  text "3" at -10.805,89.733 h1.52
  text "2" at 61.795,89.733 h1.52
  text "1" at 132.595,89.733 h1.52
  text "D" at 165.985,70.593 h1.52
  text "D" at -114.126,69.388 h1.52
  text "C" at -114.126,21.893 h1.52
  text "C" at 165.985,20.293 h1.52
  text "B" at -114.126,-25.707 h1.52
  text "B" at 165.985,-26.807 h1.52
  text "A" at -114.126,-73.207 h1.52
  text "A" at 165.858,-73.207 h1.52
  text "4" at -81.893,-95.28 h1.52
  text "3" at -10.805,-95.28 h1.52
  text "2" at 61.342,-95.28 h1.52
  text "1" at 132.195,-95.28 h1.52
Mechanical 29:
  circle w0.152: c-27.951,-70.371 r0.762
  circle w0.152: c-27.951,-70.371 r1.778
  circle w0.254: c4.034,-84.828 r2.962
  lines w0.152: -30.237,-70.371 -25.665,-70.371 ; -24.319,-70.371 -16.953,-70.371 ; -23.557,-68.593 -23.531,-72.149 -17.715,-71.133 -17.715,-69.609 -23.557,-68.593
  lines w0.2: -111.932,-73.902 -31.932,-73.902 ; -111.932,-64.902 -31.932,-64.902 ; -111.882,-77.538 8.082,-77.538 ; -101.932,-73.902 -101.932,-64.902 ; -91.932,-77.513 -91.932,-73.902 ; -12.213,-91.711 -12.213,-77.614 ; -12.213,-73.855 -12.213,-64.94 ; 8.068,-73.902 -31.932,-73.902 ; 8.068,-64.902 -31.932,-64.902 ; 8.082,-91.762 8.082,-64.838 ; -31.932,-73.902 -31.932,-64.902
  text "REV" at -103.932,-66.902 h1.52
  text "DOC NO" at -33.932,-66.902 h1.52
  text "SIZE" at 6.068,-66.902 h1.52
  text "PROJECTION" at -13.229,-67.251 h1.52
  text "A" at -103.653,-71.823 h2.54
  text "BRD4314A" at -36.432,-72.276 h2.54
  text "A4" at 3.418,-72.276 h2.54
  text "SHEET" at -92.932,-75.902 h1.52
  text "REF" at 6.068,-75.902 h1.52
  text "2 of 2" at -102.62,-76.875 h1.52
  text "This drawing is confidential and is supplied on the express" at -12.695,-80.51 h1.52
  text "condition that it shall not be loaned, copied or disclosed to any" at -12.695,-83.05 h1.52
  text "other person or used for any purpose without the written consent of" at -12.695,-85.59 h1.52
  text "C" at 4.628,-85.844 h2.03
  text "2020" at -0.452,-85.996 h2.54
  text "SILICON LABS" at -13.127,-89.882 h2.54
Mechanical 30:
  lines w0.2: 42.874,-64.838 42.874,-43.998 162.874,-43.998 ; 42.874,-60.902 82.874,-60.902 ; 42.874,-56.902 82.874,-56.902 162.874,-56.903 ; 42.874,-52.902 82.874,-52.902 ; 82.874,-48.902 162.874,-48.902 ; 82.881,-64.838 82.881,-43.998
  text "CUSTOMER" at 83.983,-45.915 h1.27
  text "PROJECT NO" at 44.359,-46.931 h1.52
  text "SILICON LABS" at 101.763,-47.439 h2.03
  text "DRAWING TITLE" at 84.212,-50.843 h1.52
  text "BRD4314A" at 45.629,-51.376 h3.3
  text "DATE" at 44.359,-55.059 h1.52
  text "BGM220P Low Cost Kit" at 87.387,-55.106 h2.03
  text ".Print_Date" at 62.647,-56.075 h1.52
  text "SHEET NAME" at 84.008,-58.996 h1.52
  text "DRAWN" at 44.359,-59.123 h1.52
  text "CHECK" at 44.359,-63.187 h1.52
